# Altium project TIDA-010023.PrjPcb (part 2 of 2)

## Sheet TIDA-010023_MCU.SchDoc
size 431 x 279 mm; Date: Not shown in title block; ApprovedBy: Not shown in title block; CheckedBy: Not shown in title block; Author: Not shown in title block; CompanyName: Not shown in title block; Engineer: Not shown in title block; Organization: Not shown in title block; Address1: Not shown in title block; Address2: Not shown in title block; Address3: Not shown in title block; Address4: Not shown in title block; DocumentNumber: 1; Revision: Use project parameter SCH_Rev; SheetNumber: 2; SheetTotal: 3; PageSetup: Record=PageOptions¦CenterHorizontal=True¦CenterVertical=True¦PrintScale=1.00¦XCorrection=1.00¦YCorrection=1.00¦PrintKind=0¦BorderSize=5000000¦LeftOffset=0¦BottomOffset=0¦Orientation=2¦PaperLength=1000¦PaperWidth=1000¦Scale=100¦PaperSource=15¦PrintQuality=600¦MediaType=1¦DitherType=10¦PaperKind=Letter¦PrintScaleMode=1
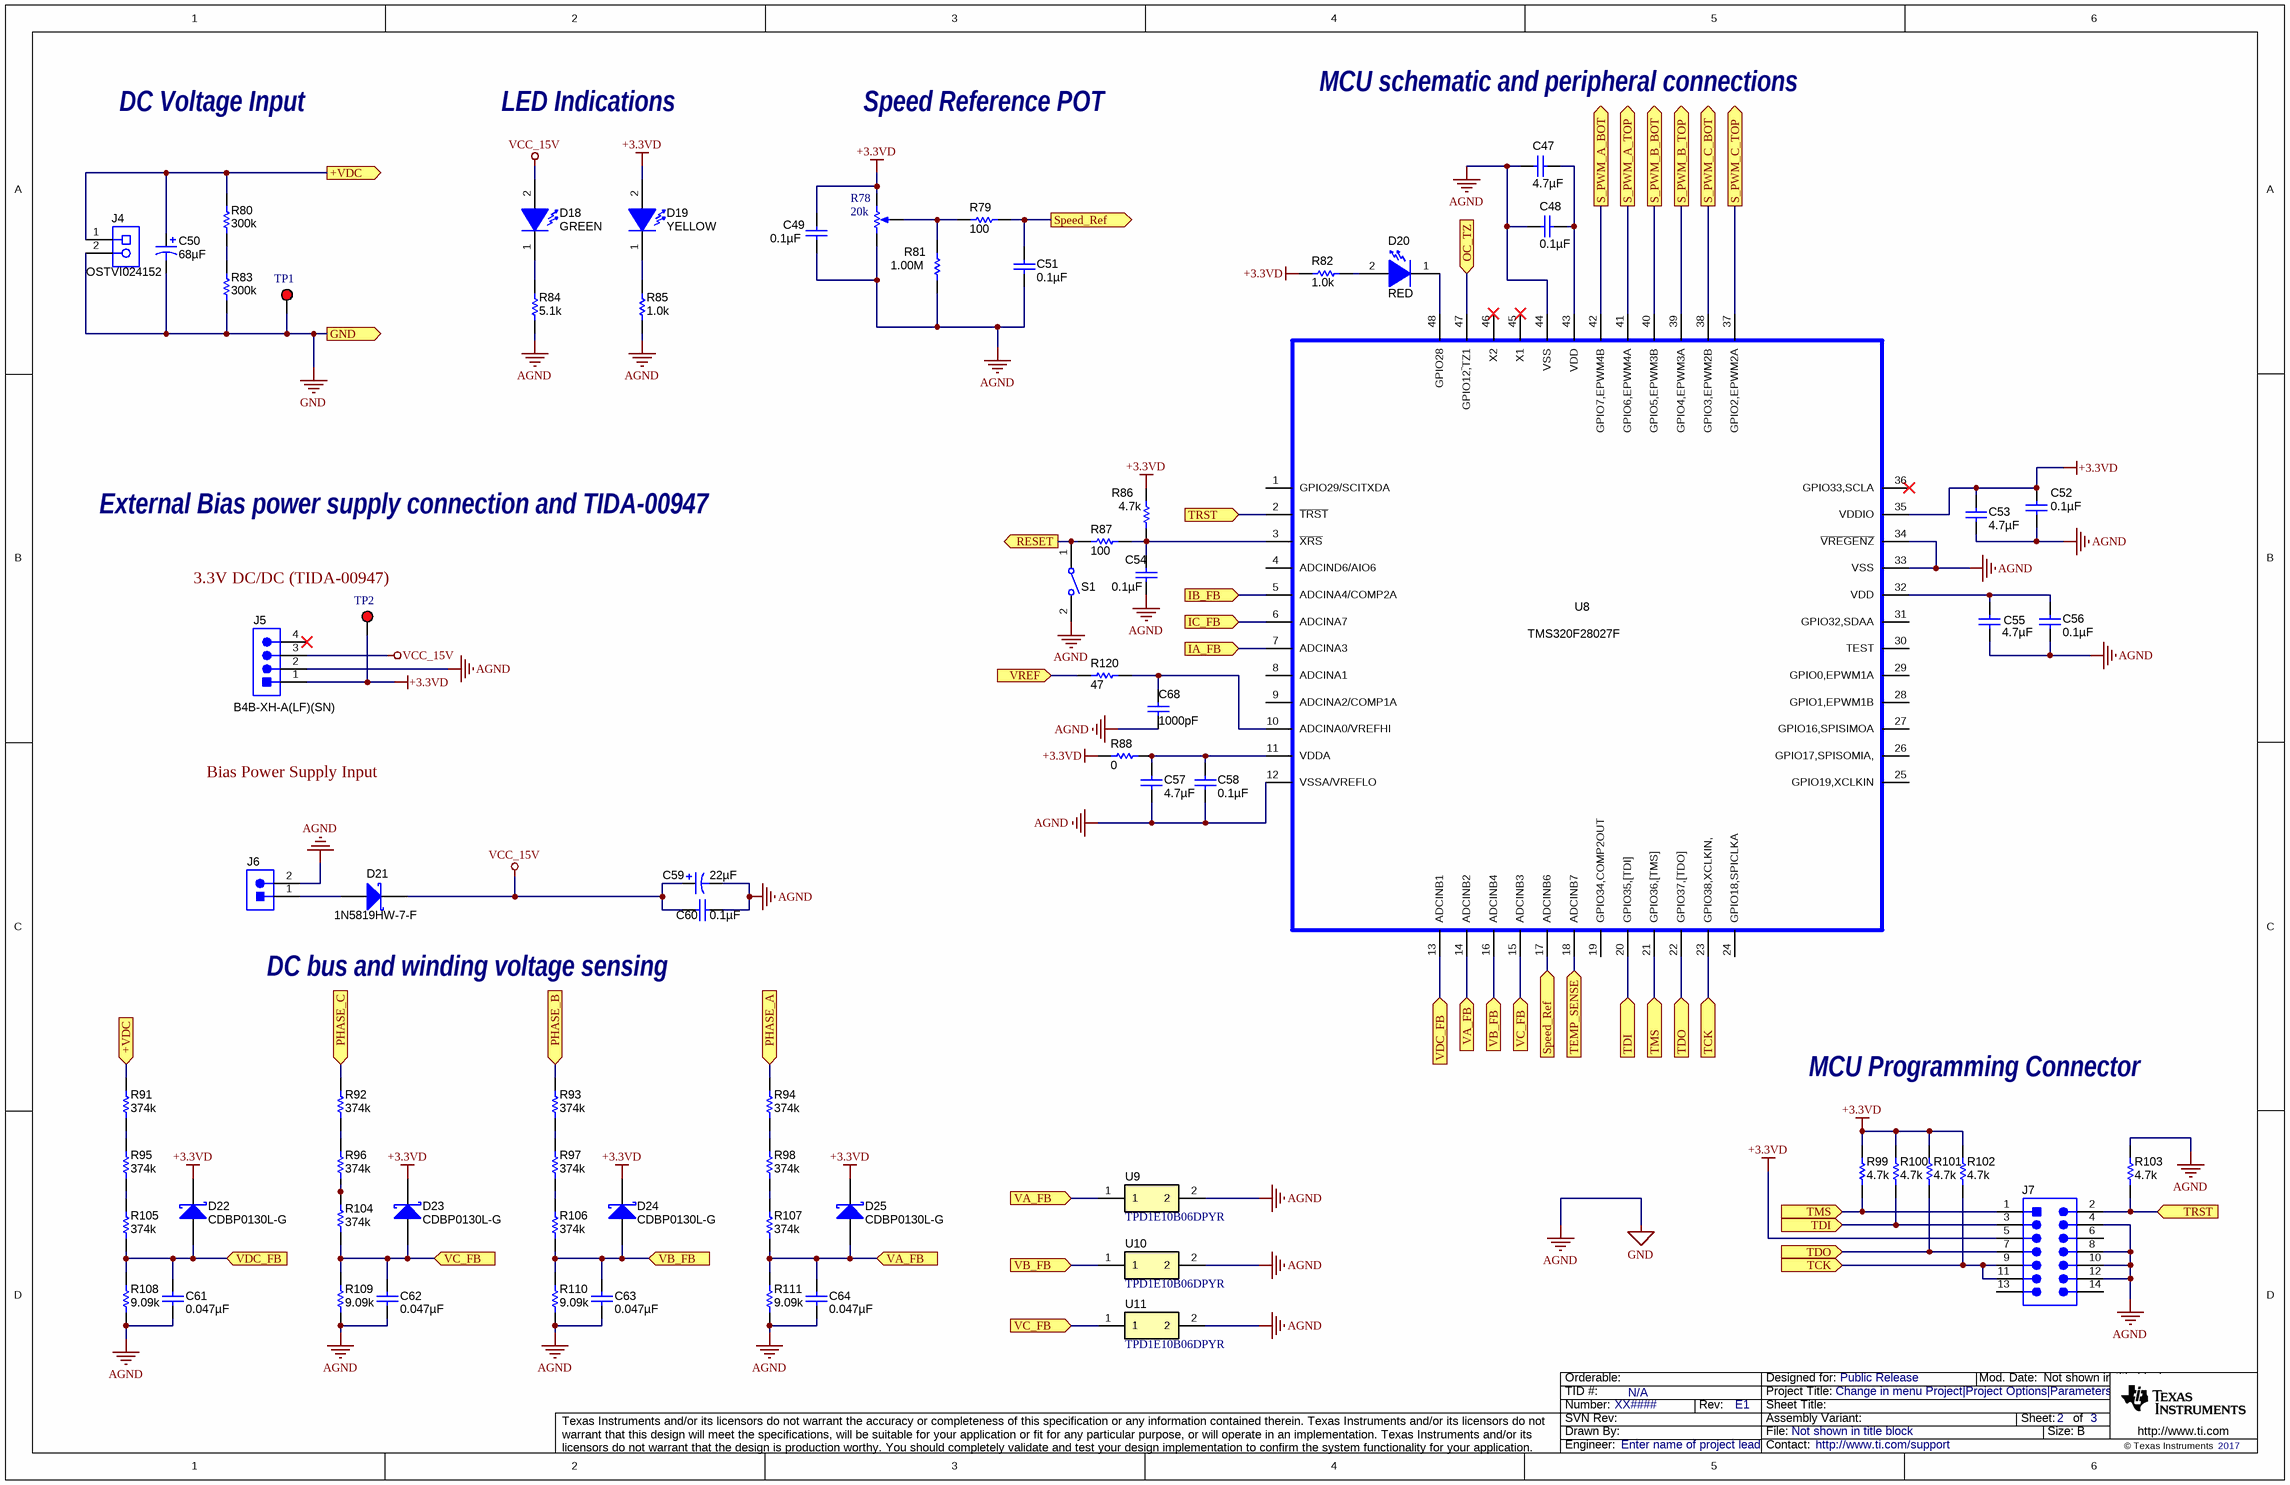
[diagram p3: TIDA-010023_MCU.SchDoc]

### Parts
C47  ValueDisplayed: 4.7µF  [0805_HV]  (hidden comment: GRM21BR71C475KA73L)
C48  ValueDisplayed: 0.1µF  [0603]  (hidden comment: 0603YC104JAT2A)
C49  ValueDisplayed: 0.1µF  [0603]  (hidden comment: 0603YC104JAT2A)
C50  ValueDisplayed: 68µF  [CS_1800x3150]  (hidden comment: UCS2W680MHD)
C51  ValueDisplayed: 0.1µF  [0603]  (hidden comment: 0603YC104JAT2A)
C52  ValueDisplayed: 0.1µF  [0603]  (hidden comment: 0603YC104JAT2A)
C53  ValueDisplayed: 4.7µF  [0805_HV]  (hidden comment: GRM21BR71C475KA73L)
C54  ValueDisplayed: 0.1µF  [0603]  (hidden comment: 0603YC104JAT2A)
C55  ValueDisplayed: 4.7µF  [0805_HV]  (hidden comment: GRM21BR71C475KA73L)
C56  ValueDisplayed: 0.1µF  [0603]  (hidden comment: 0603YC104JAT2A)
C57  ValueDisplayed: 4.7µF  [0805_HV]  (hidden comment: GRM21BR71C475KA73L)
C58  ValueDisplayed: 0.1µF  [0603]  (hidden comment: 0603YC104JAT2A)
C59  ValueDisplayed: 22µF  [RZ_500x900]  (hidden comment: URZ1E220MDD1TD)
C60  ValueDisplayed: 0.1µF  [0603]  (hidden comment: 06033C104KAT2A)
C61  ValueDisplayed: 0.047µF  [0603]  (hidden comment: 06033C473JAT2A)
C62  ValueDisplayed: 0.047µF  [0603]  (hidden comment: 06033C473JAT2A)
C63  ValueDisplayed: 0.047µF  [0603]  (hidden comment: 06033C473JAT2A)
C64  ValueDisplayed: 0.047µF  [0603]  (hidden comment: 06033C473JAT2A)
C68  ValueDisplayed: 1000pF  [0603]  (hidden comment: 06035A221FAT2A)
D18  value GREEN  [WL-SMCW_GREEN]  (hidden comment: 150060GS75000)
D19  value YELLOW  [WL-SMCW_GREEN]  (hidden comment: 150060GS75000)
D20  value RED  [WL-SMCW_GREEN]  (hidden comment: 150060GS75000)
D21  1N5819HW-7-F  [SOD-123]
D22  CDBP0130L-G  [SOD-723]
D23  CDBP0130L-G  [SOD-723]
D24  CDBP0130L-G  [SOD-723]
D25  CDBP0130L-G  [SOD-723]
J4  OSTVI024152  [Phoenix_1707027]
J5  B4B-XH-A(LF)(SN)  [JST_B4B-XH-A]
J6  0353120360  [JST_B3B-XH-A]  (value not drawn)
J7  PEC07DAAN  [CONN_PEC07DAAN]  (value not drawn)
R78  value 20k  [BOURNS_3386P]  (hidden comment: 3386P-1-203LF)
R79  ValueDisplayed: 100  [0603]  (hidden comment: CRCW0603100RFKEA)
R80  ValueDisplayed: 300k  [1206]  (hidden comment: CRCW1206300KJNEA)
R81  ValueDisplayed: 1.00M  [0603]  (hidden comment: CRCW06031M00FKEA)
R82  ValueDisplayed: 1.0k  [0603]  (hidden comment: CRCW06031K00FKEA)
R83  ValueDisplayed: 300k  [1206]  (hidden comment: CRCW1206300KJNEA)
R84  ValueDisplayed: 5.1k  [0603]  (hidden comment: CR0603-FX-4991ELF)
R85  ValueDisplayed: 1.0k  [0603]  (hidden comment: CRCW06031K00FKEA)
R86  ValueDisplayed: 4.7k  [0603]  (hidden comment: CRCW06034K70JNEA)
R87  ValueDisplayed: 100  [0603]  (hidden comment: CRCW0603100RFKEA)
R88  ValueDisplayed: 0  [0603]  (hidden comment: CRCW06030000Z0EA)
R91  ValueDisplayed: 374k  [1206]  (hidden comment: RC1206FR-07374KL)
R92  ValueDisplayed: 374k  [1206]  (hidden comment: RC1206FR-07374KL)
R93  ValueDisplayed: 374k  [1206]  (hidden comment: RC1206FR-07374KL)
R94  ValueDisplayed: 374k  [1206]  (hidden comment: RC1206FR-07374KL)
R95  ValueDisplayed: 374k  [1206]  (hidden comment: RC1206FR-07374KL)
R96  ValueDisplayed: 374k  [1206]  (hidden comment: RC1206FR-07374KL)
R97  ValueDisplayed: 374k  [1206]  (hidden comment: RC1206FR-07374KL)
R98  ValueDisplayed: 374k  [1206]  (hidden comment: RC1206FR-07374KL)
R99  ValueDisplayed: 4.7k  [0603]  (hidden comment: CRCW06034K70JNEA)
R100  ValueDisplayed: 4.7k  [0603]  (hidden comment: CRCW06034K70JNEA)
R101  ValueDisplayed: 4.7k  [0603]  (hidden comment: CRCW06034K70JNEA)
R102  ValueDisplayed: 4.7k  [0603]  (hidden comment: CRCW06034K70JNEA)
R103  ValueDisplayed: 4.7k  [0603]  (hidden comment: CRCW06034K70JNEA)
R104  ValueDisplayed: 374k  [1206]  (hidden comment: RC1206FR-07374KL)
R105  ValueDisplayed: 374k  [1206]  (hidden comment: RC1206FR-07374KL)
R106  ValueDisplayed: 374k  [1206]  (hidden comment: RC1206FR-07374KL)
R107  ValueDisplayed: 374k  [1206]  (hidden comment: RC1206FR-07374KL)
R108  ValueDisplayed: 9.09k  [0603]  (hidden comment: CRCW06039K09FKEA)
R109  ValueDisplayed: 9.09k  [0603]  (hidden comment: CRCW06039K09FKEA)
R110  ValueDisplayed: 9.09k  [0603]  (hidden comment: CRCW06039K09FKEA)
R111  ValueDisplayed: 9.09k  [0603]  (hidden comment: CRCW06039K09FKEA)
R120  ValueDisplayed: 47  [0603]  (hidden comment: CRCW0603100RFKEA)
S1  434121025816  [SW_434121025816]  (value not drawn)
TP1  5000  [Keystone5000]  (value not drawn)
TP2  5000  [Keystone5000]  (value not drawn)
U8  TMS320F28027F  [PT-48]
U9  TPD1E10B06DPYR  [DPY0002A]
U10  TPD1E10B06DPYR  [DPY0002A]
U11  TPD1E10B06DPYR  [DPY0002A]

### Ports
+VDC (in), +VDC (out), GND (out), IA_FB (in), IB_FB (in), IC_FB (in), OC_TZ (in), PHASE_A (in), PHASE_B (in), PHASE_C (in), RESET (out), S_PWM_A_BOT (out), S_PWM_A_TOP (out), S_PWM_B_BOT (out), S_PWM_B_TOP (out), S_PWM_C_BOT (out), S_PWM_C_TOP (out), Speed_Ref (in), Speed_Ref (out), TCK (in), TDI (in), TDO (in), TEMP_SENSE (in), TMS (in), TRST (in), VA_FB (in), VB_FB (in), VC_FB (in), VDC_FB (in), VREF (in)

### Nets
+3.3VD: C49.2 C52.1 C53.1 D19.2(A) D22.1(K) D23.1(K) D24.1(K) D25.1(K) J5.1 J7.5 R78.3(CW) R82.2 R86.2 R88.2 R99.2 R100.2 R101.2 R102.2 TP2.1 U8.35(VDDIO)
AGND: C47.1 C48.1 C49.1 C50.2(-) C51.1 C52.2 C53.2 C54.2 C55.2 C56.2 C57.2 C58.2 C59.2(-) C60.2 C61.2 C62.2 C63.2 C64.2 C68.2 J4.2 J5.2 J6.2 J7.4 J7.8 J7.10 J7.12 R78.1(CCW) R81.1 R83.1 R84.1 R85.1 R103.2 R108.1 R109.1 R110.1 R111.1 S1.2 TP1.1 U8.12(VSSA/VREFLO) U8.33(VSS) U8.34(~{VREGENZ}) U8.44(VSS) U9.2 U10.2 U11.2 ; port GND  [also labelled GND]
VCC_15V: C59.1(+) C60.1 D18.2(A) D21.1(K) J5.3
+VDC: C50.1(+) J4.1 R80.2 R91.2 ; port +VDC
IA_FB: U8.7(ADCINA3) ; port IA_FB
IB_FB: U8.5(ADCINA4/COMP2A) ; port IB_FB
IC_FB: U8.6(ADCINA7) ; port IC_FB
OC_TZ: U8.47(GPIO12~{,}TZ1) ; port OC_TZ
PHASE_A: R94.2 ; port PHASE_A
PHASE_B: R93.2 ; port PHASE_B
PHASE_C: R92.2 ; port PHASE_C
RESET: R87.1 S1.1 ; port RESET
S_PWM_A_BOT: U8.42(GPIO7,EPWM4B) ; port S_PWM_A_BOT
S_PWM_A_TOP: U8.41(GPIO6,EPWM4A) ; port S_PWM_A_TOP
S_PWM_B_BOT: U8.40(GPIO5,EPWM3B) ; port S_PWM_B_BOT
S_PWM_B_TOP: U8.39(GPIO4,EPWM3A) ; port S_PWM_B_TOP
S_PWM_C_BOT: U8.38(GPIO3,EPWM2B) ; port S_PWM_C_BOT
S_PWM_C_TOP: U8.37(GPIO2,EPWM2A) ; port S_PWM_C_TOP
Speed_Ref: C51.2 R79.2 U8.17(ADCINB6) ; port Speed_Ref
TCK: J7.9 J7.11 R102.1 U8.23(GPIO38,XCLKIN,) ; port TCK
TDI: J7.3 R100.1 U8.20(GPIO35,[TDI]) ; port TDI
TDO: J7.7 R101.1 U8.22(GPIO37,[TDO]) ; port TDO
TEMP_SENSE: U8.18(ADCINB7) ; port TEMP_SENSE
TMS: J7.1 R99.1 U8.21(GPIO36,[TMS]) ; port TMS
TRST: J7.2 R103.1 U8.2(~{TRST}) ; port TRST
VA_FB: C64.1 D25.2(A) R107.1 R111.2 U8.14(ADCINB2) U9.1 ; port VA_FB
VB_FB: C63.1 D24.2(A) R106.1 R110.2 U8.16(ADCINB4) U10.1 ; port VB_FB
VC_FB: C62.1 D23.2(A) R104.1 R109.2 U8.15(ADCINB3) U11.1 ; port VC_FB
VDC_FB: C61.1 D22.2(A) R105.1 R108.2 U8.13(ADCINB1) ; port VDC_FB
VREF: R120.1 ; port VREF
NetC47_2: C47.2 C48.2 U8.43(VDD)
NetC54_1: C54.1 R86.1 R87.2 U8.3(~{XRS})
NetC55_1: C55.1 C56.1 U8.32(VDD)
NetC57_1: C57.1 C58.1 R88.1 U8.11(VDDA)
NetC68_1: C68.1 R120.2 U8.10(ADCINA0/VREFHI)
NetD18_1: D18.1(K) R84.2
NetD19_1: D19.1(K) R85.2
NetD20_1: D20.1(K) U8.48(GPIO28)
NetD20_2: D20.2(A) R82.1
NetD21_2: D21.2(A) J6.1
NetR78_2: R78.2(WIPER) R79.1 R81.2
NetR80_1: R80.1 R83.2
NetR91_1: R91.1 R95.2
NetR92_1: R92.1 R96.2
NetR93_1: R93.1 R97.2
NetR94_1: R94.1 R98.2
NetR95_1: R95.1 R105.2
NetR96_1: R96.1 R104.2
NetR97_1: R97.1 R106.2
NetR98_1: R98.1 R107.2

Not connected (* = marked no-connect by the designer): J5 4*; J7 6 13 14; U8 1(GPIO29/SCITXDA) 4(ADCIND6/AIO6) 8(ADCINA1) 9(ADCINA2/COMP1A) 19(GPIO34,COMP2OUT) 24(GPIO18,SPICLKA) 25(GPIO19,XCLKIN) 26(GPIO17,SPISOMIA,) 27(GPIO16,SPISIMOA) 28(GPIO1,EPWM1B) 29(GPIO0,EPWM1A) 30(TEST) 31(GPIO32,SDAA) 36(GPIO33,SCLA)* 45(X1)* 46(X2)*

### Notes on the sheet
- MCU schematic and peripheral connections
- DC Voltage Input
- LED Indications
- Speed Reference POT
- External Bias power supply connection and TIDA-00947
- 3.3V DC/DC (TIDA-00947)
- Bias Power Supply Input
- DC bus and winding voltage sensing
- MCU Programming Connector

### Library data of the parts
C47 C53 C55 C57 = GRM21BR71C475KA73L: CAP, CERM, 4.7 µF, 16 V, +/- 10%, X7R, 0805; Manufacturer: MuRata; Polarized: N; CompType: Capacitor; Value: 4.7uF; U/M: EA; Cap_F: 0.0000047; Tolerance_%: 10; ESR_ohm: 0.006; Value1: 0.006 ohm; VDC_V: 16; Value2: 16V; TaMin_C: -55; TaMax_C: 125; Cap_Case: 0805; SizeArea_mm2: 2.5; SizeAreaWB_mm2: 6.75; SizeX_mm: 2; SizeY_mm: 1.25; SizeZ_mm: 1.45; AEC Category: Q200
C48 C52 C54 C56 C58 = 0603YC104JAT2A: CAP, CERM, 0.1 µF, 16 V, +/- 5%, X7R, 0603; Manufacturer: AVX; Polarized: N; CompType: Capacitor; Value: 0.1uF; U/M: EA; Cap_F: 0.0000001; Tolerance_%: 5; ESR_ohm: 0.039; Value1: 0.039 ohm; VDC_V: 16; Value2: 16V; TaMin_C: -55; TaMax_C: 125; SizeArea_mm2: 1.28; SizeAreaWB_mm2: 4.68; SizeX_mm: 1.6; SizeY_mm: 0.8; SizeZ_mm: 1; AEC Category: Q200
C49 C51 = 0603YC104JAT2A: CAP, CERM, 0.1 µF, 16 V, +/- 5%, X7R, 0603; Manufacturer: AVX; Polarized: N; CompType: Capacitor; Value: 0.1uF; U/M: EA; Cap_F: 0.0000001; Tolerance_%: 5; ESR_ohm: 0.039; Value1: 0.039 ohm; VDC_V: 16; Value2: 16V; TaMin_C: -55; TaMax_C: 125
C50 = UCS2W680MHD: CAP, AL, 68 µF, 450 V, +/- 20%, TH; Manufacturer: Nichicon; Polarized: Y; CompType: Capacitor; Value: 68uF; U/M: EA; Cap_F: 0.000068; Tolerance_%: 20; Value1: Unknown; VDC_V: 450; Value2: 450V; IRMS_A: 1.575; TaMin_C: -25; TaMax_C: 105; Cap_Case: 18x31.5mm; AEC Category: Q200; AEC Qualified: N
C59 = URZ1E220MDD1TD: CAP, AL, 22 µF, 25 V, +/- 20%, TH; Manufacturer: Nichicon; Polarized: Y; CompType: Capacitor; Value: 22uF; U/M: EA; Cap_F: 0.000022; Tolerance_%: 20; Value1: Unknown; VDC_V: 25; Value2: 25V; IRMS_A: 0.055; TaMin_C: -55; TaMax_C: 105; Cap_Case: 5x9mm; AEC Category: Q200
C60 = 06033C104KAT2A: CAP, CERM, 0.1 µF, 25 V, +/- 10%, X7R, 0603; Manufacturer: AVX; Polarized: N; CompType: Capacitor; Value: 0.1uF; U/M: EA; Cap_F: 0.0000001; Tolerance_%: 10; ESR_ohm: 0.05; Value1: 0.05 ohm; VDC_V: 25; Value2: 25V; TaMin_C: -55; TaMax_C: 125
C61-C64 = 06033C473JAT2A: CAP, CERM, 0.047 µF, 25 V, +/- 5%, X7R, 0603; Manufacturer: AVX; Polarized: N; CompType: Capacitor; Value: 0.047uF; U/M: EA; Cap_F: 0.000000047; Tolerance_%: 5; ESR_ohm: 0.052; Value1: 0.052 ohm; VDC_V: 25; Value2: 25V; TaMin_C: -55; TaMax_C: 125; SizeArea_mm2: 1.28; SizeAreaWB_mm2: 4.68; SizeX_mm: 1.6; SizeY_mm: 0.8; SizeZ_mm: 1; AEC Category: Q200
C68 = 06035A221FAT2A: CAP, CERM, 220 pF, 50 V, +/- 1%, C0G/NP0, 0603; Manufacturer: AVX; Polarized: N; CompType: Capacitor; Value: 220pF; U/M: EA; Cap_F: 0.00000000022; Tolerance_%: 1; ESR_ohm: 0.083; Value1: 0.083 ohm; VDC_V: 50; Value2: 50V; TaMin_C: -55; TaMax_C: 125
D18 = 150060GS75000: LED, Green, SMD; Manufacturer: Wurth Elektronics Inc; Type: InGaN; Vf_V: 3.2; Value2: 3.2V; Io_A: 0.02; Tjmax_C: 85; Value1: W; Angle: 140; U/M: EA
D19 = 150060GS75000: LED YELLOW CLEAR 0603 SMD; Manufacturer: Wurth Elektronics Inc; PartNumber: 150060YS75000; Type: InGaN; Vf_V: 2V; Io_A: 0.02; Tjmax_C: 85; Value1: W; Angle: 140; U/M: EA
D20 = 150060GS75000: LED RED CLEAR 0603 SMD; Manufacturer: Wurth Elektronics Inc; PartNumber: 150060RS75000; Type: InGaN; Vf_V: 3.2; Value2: 2V; Io_A: 0.02; Tjmax_C: 85; Value1: W; Angle: 140; U/M: EA
D21 = 1N5819HW-7-F: Diode, Schottky, 40V, 1A, SOD-123; Manufacturer: Diodes Inc.; U/M: EA; Vf_V: 0.45; Value2: 0.45V; Io_A: 1; Vr_V: 40; TJmax_C: 125
D22-D25 = CDBP0130L-G: Diode, Schottky, 30 V, 0.1 A, SOD-723; Manufacturer: Comchip Technology; U/M: EA; Vf_V: 0.35; Value: 30V; Value1: 0.1A; Value2: 0.35V; Io_A: 0.1; Vr_V: 30; TJmax_C: 125; SizeAreaWB_mm2: 3.84; SizeArea_mm2: 0.84; SizeX_mm: 1.4; SizeY_mm: 0.6; SizeZ_mm: 0.65; AEC Category: Q101
J4 = 1707027: TERMINAL BLOCK 7.50MM 2POS PCB; Manufacturer: On Shore Technology Inc.; SymbolCreator: a0412235; Pitch_mm: 7.62; Gender: Female; Row_Count: 1; Current_A: 16; Voltage_V: 1000; Cert_CSA: Y
J5 = B4B-XH-A(LF)(SN): Header (Shrouded), 2.5mm, 4x1, Tin, TH; Manufacturer: JST Manufacturing; SymbolCreator: a0412235; Pitch_mm: 2.5; Gender: Male; Shrouded: Y; Row_Count: 1; Current_A: 3; Voltage_V: 250
J6 = B2B-XH-A(LF)(SN): Header (Shrouded), 2.5mm, 2x1, Tin, TH; Manufacturer: JST Manufacturing; SymbolCreator: a0412235; Pitch_mm: 2.5; Gender: Male; Shrouded: Y; Row_Count: 1; Current_A: 3; Voltage_V: 250
J7 = PEC07DAAN: Header, 100mil, 7x2, Tin, TH; Manufacturer: Sullins Connector Solutions; SymbolCreator: a0412235; Pitch_mm: 2.54; Gender: Male; Shrouded: N; Row_Count: 2; Current_A: 3; Voltage_V: 1800; Cert_UL: Y
R78 = 3386P-1-203LF: TRIMMER, 20k ohm, 0.5W, TH; Manufacturer: Bourns; Sim Note: Enter the Resistance value and the set point into parameter fields.; SymbolCreator: a0412235
R79 R87 = CRCW0603100RFKEA: RES, 100, 1%, 0.1 W, 0603; Manufacturer: Vishay-Dale; CompType: Resistor; Value: 100; Value_Code: 100R; Tolerance_%: 1; Power_W: 0.1; Value2: 0.1W; VDC_V: 75; TempCo: 100 ppm/C; EIA_Code: E96; U/M: EA; SizeArea_mm2: 1.28; SizeX_mm: 1.6; SizeY_mm: 0.8; AEC Category: Q200
R80 R83 = CRCW1206300KJNEA: RES, 300 k, 5%, 0.25 W, 1206; Manufacturer: Vishay-Dale; CompType: Resistor; Value: 300k; Res_ohm: 300000; Tolerance_%: 5; Power_W: 0.25; Value2: 0.25W; VDC_V: 200; TempCo: 200 ppm/C; EIA_Code: E24; U/M: EA; SizeArea_mm2: 5.12; SizeX_mm: 3.2; SizeY_mm: 1.6; SizeZ_mm: 1.35; AEC Category: Q200
R81 = CRCW06031M00FKEA: RES, 1.00 M, 1%, 0.1 W, 0603; Manufacturer: Vishay-Dale; CompType: Resistor; Value: 1.00Meg; Res_ohm: 1000000; Value_Code: 1M00; Tolerance_%: 1; Power_W: 0.1; Value2: 0.1W; VDC_V: 75; TempCo: 100 ppm/C; EIA_Code: E96; U/M: EA; SizeArea_mm2: 1.28; SizeX_mm: 1.6; SizeY_mm: 0.8; AEC Category: Q200
R82 R85 = CRCW06031K00JNEA: RES, 1.0 k, 5%, 0.1 W, 0603; Manufacturer: Vishay-Dale; CompType: Resistor; Value: 1.0k; Res_ohm: 1000; Value_Code: 1k00; Tolerance_%: 5; Power_W: 0.1; Value2: 0.1W; VDC_V: 75; TempCo: 200 ppm/C; SizeArea_mm2: 1.28; SizeX_mm: 1.6; SizeY_mm: 0.8; SizeZ_mm: 1; EIA_Code: E24; U/M: EA; AEC Category: Q200; Green_Lifecycle: Active; Green_REACh: Passed
R84 = CRCW06035K10JNEA: RES, 5.1 k, 5%, 0.1 W, 0603; Manufacturer: Vishay-Dale; CompType: Resistor; Value: 5.1k; Res_ohm: 5100; Value_Code: 5k10; Tolerance_%: 5; Power_W: 0.1; Value2: 0.1W; VDC_V: 75; TempCo: 200 ppm/C; SizeArea_mm2: 1.28; SizeX_mm: 1.6; SizeY_mm: 0.8; SizeZ_mm: 1; EIA_Code: E24; U/M: EA; AEC Category: Q200; Green_Lifecycle: Active; Green_REACh: Passed
R86 R99-R103 = CRCW06034K70JNEA: RES, 4.7 k, 5%, 0.1 W, 0603; Manufacturer: Vishay-Dale; CompType: Resistor; Value: 4.7k; Res_ohm: 4700; Value_Code: 4k70; Tolerance_%: 5; Power_W: 0.1; Value2: 0.1W; VDC_V: 75; TempCo: 200 ppm/C; EIA_Code: E24; U/M: EA
R88 = CRCW06030000Z0EA: RES, 0, 5%, 0.1 W, 0603; Manufacturer: Vishay-Dale; CompType: Resistor; Value: 0; Value_Code: 0000; Tolerance_%: 5; Power_W: 0.1; Value2: 0.1W; VDC_V: 75; TempCo: 200 ppm/C; SizeArea_mm2: 1.28; SizeX_mm: 1.6; SizeY_mm: 0.8; SizeZ_mm: 1; EIA_Code: E24; U/M: EA; AEC Category: Q200
R91-R98 R104-R107 = RC1206FR-07374KL: RES, 374 k, 1%, 0.25 W, 1206; Manufacturer: Yageo America; CompType: Resistor; Value: 374k; Res_ohm: 374000; Tolerance_%: 1; Power_W: 0.25; Value2: 0.25W; VDC_V: 200; TempCo: 100 ppm/C; EIA_Code: E96; U/M: EA; SizeArea_mm2: 5.12; SizeX_mm: 3.2; SizeY_mm: 1.6; SizeZ_mm: 1.35; AEC Category: Q200
R108-R111 = CRCW06039K09FKEA: RES, 9.09 k, 1%, 0.1 W, 0603; Manufacturer: Vishay-Dale; CompType: Resistor; Res_ohm: 9090; Value: 9.09k; Value_Code: 9k09; Tolerance_%: 1; Power_W: 0.1; Value2: 0.1W; VDC_V: 75; TempCo: 100 ppm/C; EIA_Code: E96; U/M: EA; SizeArea_mm2: 1.28; SizeX_mm: 1.6; SizeY_mm: 0.8; AEC Category: Q200
R120 = CRCW060347R0JNEA: RES, 47, 5%, 0.1 W, 0603; Manufacturer: Vishay-Dale; CompType: Resistor; Value: 47; Value_Code: 47R0; Tolerance_%: 5; Power_W: 0.1; Value2: 0.1W; VDC_V: 75; TempCo: 200 ppm/C; SizeArea_mm2: 1.28; SizeX_mm: 1.6; SizeY_mm: 0.8; SizeZ_mm: 1; EIA_Code: E24; U/M: EA; AEC Category: Q200; Green_Lifecycle: Active; Green_REACh: Passed
S1 = 434121025816: Switch, Tactile, SPST, 12 V, SMD; Manufacturer: Wurth Elektronik; SymbolCreator: a0799628; VDC_V: 12; SwitchFunction: Off-On; PositionCount: 1; CurrentRating_mA: 50
TP1 TP2 = 5000: Test Point, Miniature, Red, TH; Manufacturer: Keystone; CompType: Test Point Loop; ContactFinish: Silver
U8 = TMS320F2802XPTA: IC, 32-Bit Piccolo Microcontrollers, xx MHz; PartNumber: TMS320F28027FPTT; Manufacturer: TI; Alternate Manufacturer: None; Area: 114.90 mm
U9-U11 = TPD1E10B06DPYR: ESD in 0402 Package with 10 pF Capacitance and 6 V Breakdown, 1 Channel, -40 to +125 degC, 2-pin X2SON (DPY), Green (RoHS & no Sb/Br); Manufacturer: Texas Instruments; Alternate PartNumber: Equivalent; Breakdown Voltage(Min)(V): 6; Eco-Plan: TBD; IEC 61000-4-2 Air-Gap(+/- kV): 30; IO Capacitance(Typ)(pF): 10; SubFamily: ESD Solution

## Sheet TIDA-010023_CoverSheet.SchDoc
size 431 x 279 mm; Date: Not shown in title block; ApprovedBy: Not shown in title block; CheckedBy: Not shown in title block; Author: Not shown in title block; CompanyName: Not shown in title block; Engineer: Not shown in title block; Organization: Not shown in title block; Address1: Not shown in title block; Address2: Not shown in title block; Address3: Not shown in title block; Address4: Not shown in title block; DocumentNumber: 1; Revision: Use project parameter SCH_Rev; SheetNumber: 1; SheetTotal: 3; PageSetup: Record=PageOptions¦CenterHorizontal=True¦CenterVertical=True¦PrintScale=1.00¦XCorrection=1.00¦YCorrection=1.00¦PrintKind=0¦BorderSize=5000000¦LeftOffset=0¦BottomOffset=0¦Orientation=2¦PaperLength=1000¦PaperWidth=1000¦Scale=100¦PaperSource=15¦PrintQuality=600¦MediaType=1¦DitherType=10¦PaperKind=Letter¦PrintScaleMode=1
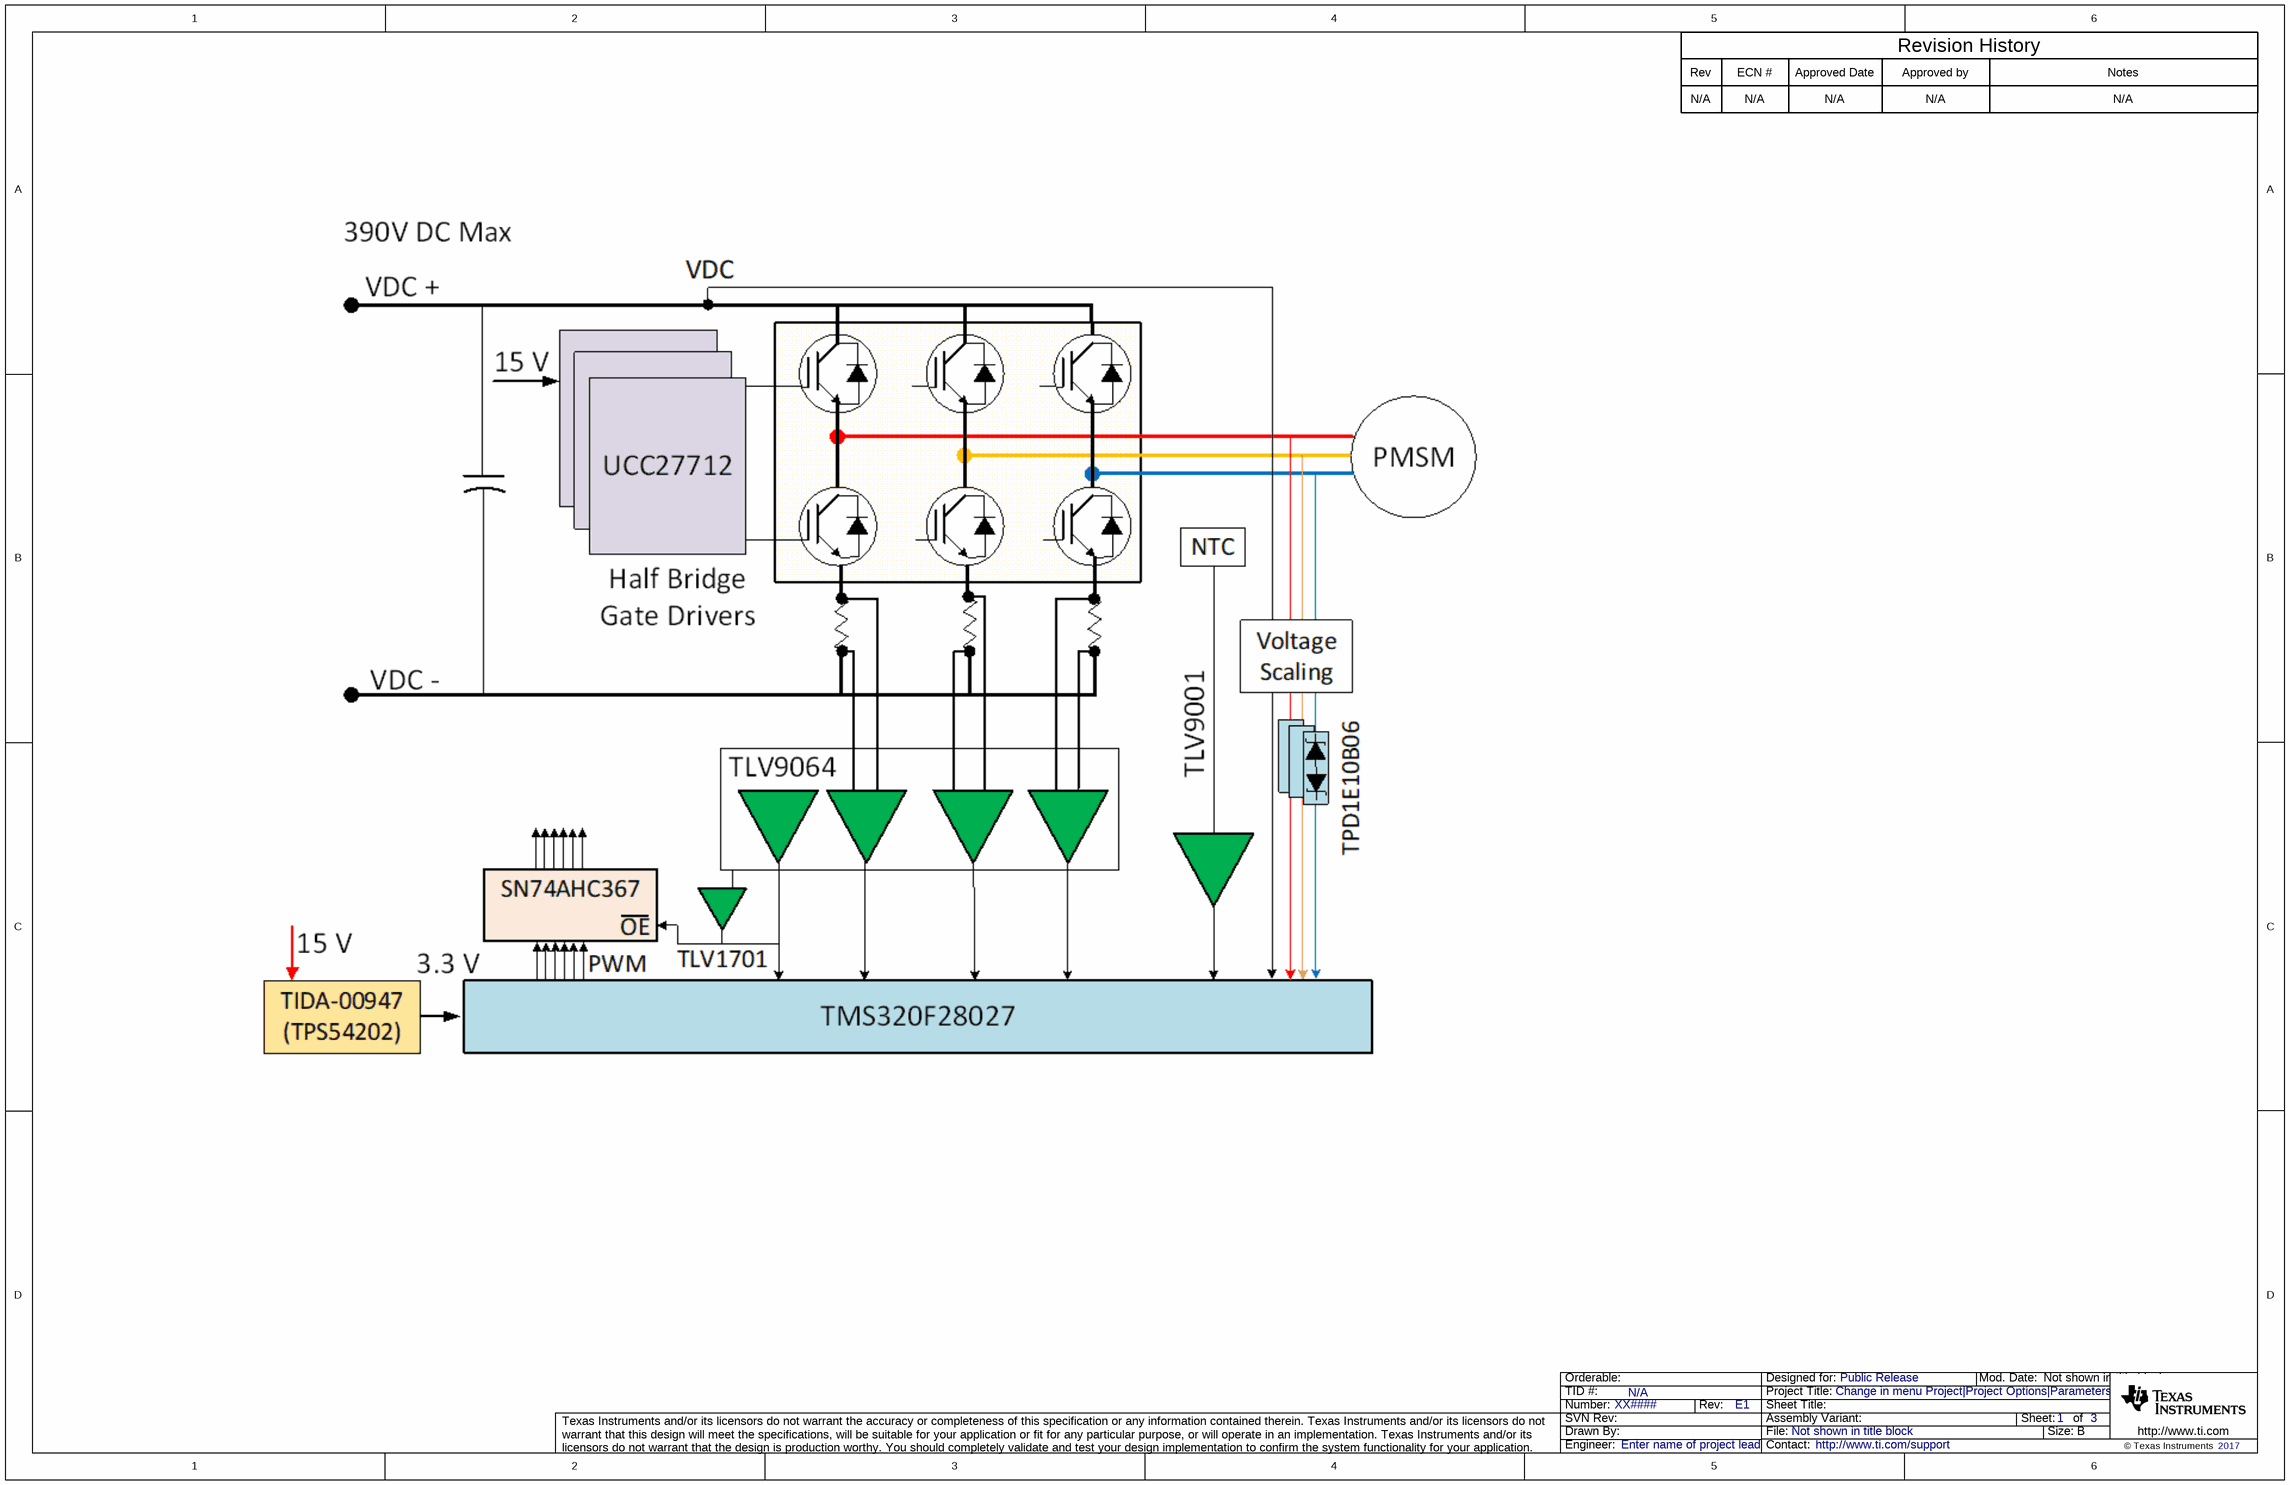
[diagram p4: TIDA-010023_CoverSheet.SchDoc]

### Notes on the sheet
- Rev
- N/A
- ECN #
- Approved Date
- Approved by
- Revision History
- Notes

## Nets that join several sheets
+3.3VD: TIDA-010023_Current_Sensing (13 pins), TIDA-010023_Inverter (C39.1 R63.1 U7.5), TIDA-010023_MCU (20 pins)
AGND: TIDA-010023_Current_Sensing (21 pins), TIDA-010023_Inverter (41 pins), TIDA-010023_MCU (45 pins)
VCC_15V: TIDA-010023_Inverter (R32.2 R42.2 R61.2), TIDA-010023_MCU (5 pins)
+VDC: TIDA-010023_Inverter (6 pins), TIDA-010023_MCU (C50.1 J4.1 R80.2 R91.2)
IA_FB: TIDA-010023_Current_Sensing (C5.1 D1.2 D5.1 R4.2), TIDA-010023_MCU (U8.7)
IA_N: TIDA-010023_Current_Sensing (C6.1 R5.1), TIDA-010023_Inverter (R47.2)
IA_P: TIDA-010023_Current_Sensing (C6.2 R7.1), TIDA-010023_Inverter (R43.2)
IB_FB: TIDA-010023_Current_Sensing (C13.1 D3.2 D6.1 R16.2), TIDA-010023_MCU (U8.5)
IB_N: TIDA-010023_Current_Sensing (C14.1 R17.1), TIDA-010023_Inverter (R56.2)
IB_P: TIDA-010023_Current_Sensing (C14.2 R21.1), TIDA-010023_Inverter (R51.2)
IC_FB: TIDA-010023_Current_Sensing (C19.1 D4.2 D8.1 R26.2), TIDA-010023_MCU (U8.6)
IC_N: TIDA-010023_Current_Sensing (C20.2 R27.1), TIDA-010023_Inverter (R53.1)
IC_P: TIDA-010023_Current_Sensing (C20.1 R28.1), TIDA-010023_Inverter (R46.1)
OC_TZ: TIDA-010023_Current_Sensing (Q7.3 R119.2), TIDA-010023_MCU (U8.47)
PHASE_A: TIDA-010023_Inverter (8 pins), TIDA-010023_MCU (R94.2)
PHASE_B: TIDA-010023_Inverter (8 pins), TIDA-010023_MCU (R93.2)
PHASE_C: TIDA-010023_Inverter (8 pins), TIDA-010023_MCU (R92.2)
PWM_A_BOT: TIDA-010023_Current_Sensing (U2.9), TIDA-010023_Inverter (R65.1)
PWM_A_TOP: TIDA-010023_Current_Sensing (U2.7), TIDA-010023_Inverter (R71.1)
PWM_B_BOT: TIDA-010023_Current_Sensing (U2.11), TIDA-010023_Inverter (R50.1)
PWM_B_TOP: TIDA-010023_Current_Sensing (U2.13), TIDA-010023_Inverter (R54.1)
PWM_C_BOT: TIDA-010023_Current_Sensing (U2.5), TIDA-010023_Inverter (R35.1)
PWM_C_TOP: TIDA-010023_Current_Sensing (U2.3), TIDA-010023_Inverter (R36.1)
S_PWM_A_BOT: TIDA-010023_Current_Sensing (U2.10), TIDA-010023_MCU (U8.42)
S_PWM_A_TOP: TIDA-010023_Current_Sensing (U2.6), TIDA-010023_MCU (U8.41)
S_PWM_B_BOT: TIDA-010023_Current_Sensing (U2.12), TIDA-010023_MCU (U8.40)
S_PWM_B_TOP: TIDA-010023_Current_Sensing (U2.14), TIDA-010023_MCU (U8.39)
S_PWM_C_BOT: TIDA-010023_Current_Sensing (U2.4), TIDA-010023_MCU (U8.38)
S_PWM_C_TOP: TIDA-010023_Current_Sensing (U2.2), TIDA-010023_MCU (U8.37)
TEMP_SENSE: TIDA-010023_Inverter (C44.2 R68.2), TIDA-010023_MCU (U8.18)
VREF: TIDA-010023_Current_Sensing (C18.1 R23.1 R24.2 R25.1), TIDA-010023_MCU (R120.1)

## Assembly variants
001: not fitted FID1 FID2 FID3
